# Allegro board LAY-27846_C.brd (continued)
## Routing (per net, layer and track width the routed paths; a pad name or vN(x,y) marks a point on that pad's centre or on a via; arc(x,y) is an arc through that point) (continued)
P5V0_SDA_USB_CONN_VBUS: length 4.2
  TOP w0.508: J15.1 10.26,40.46 11.32,41.52 L6.1
P5V_K24_USB: length 5
  TOP w0.178: L4.1 7.35,22.58 U10.1 7.13,20.38 J6.1
P5V_KW24_USB: length 57.6
  TOP w0.508: D15.C 13.06,20.81 v2(13.06,24.74) C50.1
  L3_PWR w0.508: J27.1 57.23,13.26 32.56,13.26 21.08,24.74 v2(13.06,24.74)
P5V_SDA: length 45
  TOP w0.508: v2(29.72,39.42) 29.72,40.97 27.18,43.51 C49.1 19.48,43.48 D13.C
  L3_PWR w0.508: v2(42.82,35.38) 42.8,35.38 v2(37.08,41.1) 30.68,41.1 29.72,40.13 v2(29.72,39.42)
  BOTTOM w0.178: v2(37.08,41.1) 37.07,41.11 U6.6 ; R52.1 29.29,38.99 v2(29.72,39.42) 28.32,39.42 TP104.1
  BOTTOM w0.508: R108.1 C33.1 C34.1 42.87,37.06 U7.1 42.12,36.08 v2(42.82,35.38)
P5V_USB: length 73.7
  TOP w0.508: v2(42.11,39.95) 42.11,46.28 v2(42.47,46.63)
  L3_PWR w0.508: v2(52.17,46.63) v2(42.47,46.63) 29.97,46.63 29.46,46.13 20.52,46.13 ; 13.7,22.41 J1.1 ; J1.1 15.31,22.41 ; J1.1 15.31,24.02 ; J1.1 13.7,24.02
  BOTTOM w0.178: J12.2 55.09,36.83 52.83,39.09 52.83,45.97 v2(52.17,46.63)
  BOTTOM w0.508: U7.6 42.12,39.94 v2(42.11,39.95) ; D12.A 16.36,16.1 15.77,16.69 15.77,21.95 J1.1 v2(14.5,27.53)
  vias: v2(6.96,44.7)
VCC: length 11.6
  TOP w0.508: J2.3 J2.1 ; J2.3 J2.5 ; J2.3 33.75,21.72 J3.2
  BOTTOM w0.33: J2.5 TP5.1
VDD_IF: length 8.1
  TOP w0.178: U3.54 69.03,30.06 70.33,31.37 C42.1 C43.1 ; C43.1 70.54,29.62 C44.1 69.98,29.06 U3.52 ; C43.1 70.28,30.35 69.49,29.56 U3.53
VDD_REGD: length 2.4
  TOP w0.178: C15.1 70.66,24.26 69.1,24.26 U3.43
CLK_OUT: length 10.3
  TOP w0.178: v2(65.96,19.48) 65.71,19.48 R83.1 ; v2(66.7,22.58) 66.7,22.91 66.7,22.91 U3.39
  BOTTOM w0.178: TP27.1 63.22,20.29 64.03,19.48 v2(65.96,19.48) 66.85,20.37 66.85,22.43 v2(66.7,22.58)
ELE_PS_SENSE: length 186.2
  TOP w0.178: v2(74.02,35.03) 73.96,35.03 73.08,35.92 73.08,55.88 74.7,57.51 74.7,63.83 75.08,64.21 75.08,65.43 v2(74.83,65.68) ; J16.D4 6.48,5.39 9.91,8.81 v2(11.28,8.81) ; v2(83.61,73.46) 83.61,76.49 83.48,76.62 J16.B4
  L2_GND w0.178: v2(74.22,9.96) 70.18,5.92 23.93,5.92 22.56,7.29 22.56,9.7 v1(19.94,12.32)
  L3_PWR w0.178: v2(74.83,65.68) 74.83,66.9 81.43,73.51 83.56,73.51 v2(83.61,73.46) ; v1(19.94,12.32) 19.94,18.64 21.31,20.02 v2(21.34,20.02) ; v2(74.02,35.03) 74.02,30.18 73.53,29.69 73.53,17.68 74.22,16.99 v2(74.22,9.96)
  BOTTOM w0.178: v2(11.28,8.81) 12.19,9.73 19.1,9.73 19.94,10.57 v1(19.94,12.32) ; v2(21.34,20.02) 21.59,20.27 37.21,20.27 38.41,21.46 38.41,25.25 40.06,26.9 R111.1
EXTAL_32: length 4.9
  TOP w0.178: R83.2 63.78,20.4 63.78,21.92 63.12,22.58 R82.2 62.7,22.59 U3.31
EXTAL_32K: length 3.7
  TOP w0.178: Y2.1 62.48,19.84 C23.1 62.69,20.8 R82.1
EXTAL_32M: length 8
  TOP w0.178: U3.1 68.2,34.54 C20.2 68.3,36.94 Y1.1 67.55,37.02 66.52,38.05 C21.1
EZP_CSR_B: length 20.2
  TOP w0.178: R27.2 2.54,45.59 1.24,46.89 1.24,52.83 2.11,53.7 J11.9 4.55,53.7 5.28,54.43 R26.2
GPIO1: length 88.9
  TOP w0.178: J16.D50 54.48,7.8 56.41,9.73 71.76,9.73 72.59,10.57 v2(72.59,19.43) ; J10.15 63.58,65.84 v1(65.02,67.28) ; v2(67.7,32.46) U3.2
  BOTTOM w0.178: v1(65.02,67.28) 65.02,67.03 67.7,64.36 v2(67.7,32.46) 67.7,31.49 72.59,26.59 v2(72.59,19.43)
GPIO2: length 92.5
  TOP w0.178: J16.D51 55.48,6.82 57.38,8.71 v2(59.41,8.71) ; v2(55.42,65.89) 55.47,65.84 J10.16 ; v2(67.89,30.58) 67.2,31.28 U3.3
  L3_PWR w0.178: v2(55.42,65.89) 65.07,65.89 v1(65.28,66.09)
  BOTTOM w0.178: v2(59.41,8.71) 70.05,8.71 71.6,10.27 71.6,26.87 v2(67.89,30.58) 67.18,31.29 67.18,64.19 v1(65.28,66.09)
GPT_VBRD: length 61.1
  TOP w0.178: J9.2 v1(65.1,56.95)
  L3_PWR w0.178: v2(26.8,56.77) 29.64,56.77 29.92,57.05 65,57.05 v1(65.1,56.95)
  BOTTOM w0.178: J8.2 12.12,60.71 22.86,60.71 v2(26.8,56.77)
GPT_VDA: length 17.4
  TOP w0.178: J9.4 64.97,58.22 64.06,57.3 v2(64.06,48.36)
  BOTTOM w0.178: R20.1 64.92,45.26 64.92,47.5 v2(64.06,48.36)
K24_USB_SHLD: length 18.9
  TOP w0.178: J6.S1 4.78,22.32 3.85,23.25 J6.S3 ; J6.S4 3.67,14.9 4.78,16 4.78,16.84
  TOP w0.508: J6.S4 1.78,14.91 ; L8.1 5.7,15.93 J6.S2 4.78,16.84
  BOTTOM w0.508: J6.S1 J6.S2
KW24_USB_DN: length 63.7
  TOP w0.178: J6.2 6.73,19.73 U11.1 7.35,19.59 v2(7.59,19.84)
  L2_GND w0.178: v2(7.59,19.84) 8.89,19.84 17.37,28.32 v2(28.14,28.32)
  L3_PWR w0.178: v2(28.14,28.32) 28.3,28.17 40.97,28.17 v2(41.88,27.25)
  BOTTOM w0.178: R33.1 53.97,29.08 51.71,26.82 51.71,22.12 50.9,21.31 48.95,21.31 44.37,25.88 42.21,25.88 41.88,26.21 v2(41.88,27.25)
KW24_USB_DP: length 59.8
  TOP w0.178: v2(7.35,18.34) U12.1 5.88,19.08 J6.3
  L2_GND w0.178: v2(27.48,27.84) 17.55,27.84 8.05,18.34 v2(7.35,18.34)
  L3_PWR w0.178: v2(27.48,27.84) 40.13,27.84 41.05,26.92 v2(41.05,26.95)
  BOTTOM w0.178: v2(41.05,26.95) 41.05,26.01 41.5,25.55 44.17,25.55 48.79,20.93 51.79,20.93 54.1,23.24 R34.1
POWER_EN: length 15.8
  L3_PWR w0.178: v2(40.94,40.77) 40.94,38.25 44.27,34.92 v2(44.27,31.52)
  BOTTOM w0.178: v2(40.94,40.77) 40.95,40.77 40.95,43.53 40.6,43.88 U6.31 ; R551.1 v2(44.27,31.52)
PTA0: length 87.9
  TOP w0.178: v2(45.24,22.48) 45.44,22.68 45.44,39.01 v2(45.19,39.27) ; U3.33 63.7,22.79 v2(63.7,22.78) ; J11.4 v2(9.5,57.51) ; v1(30.28,49.45) 30.28,49.25 34.77,44.75 v2(34.77,42.9)
  L3_PWR w0.178: v2(30.51,51.31) 20.07,51.31 13.87,57.51 v2(9.5,57.51) ; v2(34.77,42.9) 44.65,42.9 45.19,42.37 v2(45.19,39.27) ; v2(63.7,22.78) 45.54,22.78 v2(45.24,22.48)
  BOTTOM w0.178: v1(30.28,49.45) 30.51,49.68 v2(30.51,51.31) ; v2(45.19,39.27) 45.24,39.27 R93.2
PTA1: length 97.9
  TOP w0.178: J11.8 v1(10.67,54.97) ; U3.34 v2(64.2,24.79)
  L2_GND w0.178: v2(43.31,19.25) 46.28,22.23 46.28,47.32 v1(42.54,51.05)
  L3_PWR w0.178: v1(10.67,54.97) 10.67,54.05 11.86,52.86 17.88,52.86 19.91,50.83 v1(28.14,50.83) 42.32,50.83 v1(42.54,51.05) ; v2(43.31,19.25) 43.33,19.23 v2(62.03,19.23)
  BOTTOM w0.178: v2(64.2,24.79) 64.2,24.78 62.03,22.61 v2(62.03,19.23)
PTA2: length 90.9
  TOP w0.178: U3.35 v2(64.7,22.33) ; J11.6 7.75,56.11 24.28,56.11 26.97,53.42 v1(26.97,53.39)
  L3_PWR w0.178: v2(50.34,52.4) 27.97,52.4 v1(26.97,53.39) ; v2(50.9,22.33) v2(64.7,22.33)
  BOTTOM w0.178: v2(50.34,52.4) 50.34,46.38 51.89,44.83 51.89,31.14 51.23,30.48 51.23,22.63 50.93,22.33 v2(50.9,22.33)
PTA3: length 122.1
  TOP w0.178: R25.1 7.42,59.21 7.62,59 J11.2 6.35,58.78 v1(5.77,58.19) ; v2(65.2,21.87) U3.36
  L2_GND w0.178: v2(46.23,20.9) 46.69,21.36 46.69,38.51 v2(48.44,40.26)
  L3_PWR w0.178: v1(5.77,58.19) 4.5,56.92 4.5,34.34 7.67,31.17 8.89,31.17 13.49,26.57 32.61,26.57 33.86,25.32 41.4,25.32 45.83,20.9 v2(46.23,20.9) 47.2,21.87 v2(65.2,21.87)
  BOTTOM w0.178: v2(48.44,40.26) 48.44,43.38 R92.2
PTA4: length 74.1
  TOP w0.178: R27.1 v2(6.35,45.59) ; U3.37 v2(65.7,23.14)
  L3_PWR w0.178: v1(15.98,35.33) 15.98,34.47 21.59,28.85 28.73,28.85 28.96,28.63 41.17,28.63 41.71,28.09 v2(47.19,28.09) ; v2(65.7,23.14) 64.53,24.31 v2(47.19,24.31)
  BOTTOM w0.178: v1(15.98,35.33) 15.98,36.73 7.11,45.59 v2(6.35,45.59) ; v2(47.19,24.31) v2(47.19,28.09)
PTA19: length 26.5
  TOP w0.178: U3.40 v2(67.2,23.09) ; R564.2 72.01,45.16 72.59,44.58 v2(72.59,42.55)
  L3_PWR w0.178: v2(72.59,42.55) 72.59,42.57 72.77,42.39 72.77,32.87 68.45,28.55 68.45,26.67 67.59,25.81 67.59,23.48 v2(67.2,23.09)
PTB10_TWRPI: length 116.4
  TOP w0.178: v2(69.42,48.62) U13.4 68.13,50.2 R553.2 ; J10.11 v1(63.09,63.3) ; R73.1 13.18,68.19 J17.3 12.88,67.9 11.76,66.78 11.76,61.49 14.3,58.95 v2(21.67,58.95) ; J16.B9 78.48,74.39 77.95,73.86 77.95,71.35 74.35,67.74 v1(74.35,64.19)
  L2_GND w0.178: v2(44.81,59.41) 44.81,60.25 v1(48.16,63.6)
  L3_PWR w0.178: v1(48.16,63.6) 48.31,63.75 62.64,63.75 v1(63.09,63.3) 63.2,63.2 73.36,63.2 v1(74.35,64.19) ; v2(21.67,58.95) 21.72,59 28.96,59 29.36,59.41 v2(44.81,59.41)
  BOTTOM w0.178: v1(74.35,64.19) 74.35,62.76 74.78,62.33 74.78,60.48 72.72,58.42 72.72,49.25 72.09,48.62 TP506.1 v2(69.42,48.62)
PTB11_TWRPI: length 113.4
  TOP w0.178: v2(25.68,66.09) 26.26,66.67 R72.1 ; v2(69.49,46.13) 69.44,46.08 U13.2 67.34,46.08 66.62,46.79 66.62,49.71 R554.2 ; J16.B7 80.48,73.17 77.27,69.95 v2(77.27,69.98) ; v2(28.83,66.12) 28.8,66.09 v2(28.8,63.04) 29.39,62.46 43.54,62.46 v1(44.15,63.07) ; J10.12 v2(55.37,63.3)
  L3_PWR w0.178: v2(28.83,66.12) 28.8,66.09 v2(25.68,66.09) ; v2(75.74,63.32) 75.23,63.32 74.73,62.81 62.74,62.81 62.26,63.3 v2(55.37,63.3) 48.56,63.3 48.34,63.07 v1(44.15,63.07)
  BOTTOM w0.178: v2(25.68,66.09) 21.79,66.09 21.46,66.42 16.92,66.42 15.44,67.9 J17.6 ; v2(77.27,69.98) 75.74,68.45 v2(75.74,63.32) 75.74,60.6 73.66,58.52 73.66,56.59 73.08,56.01 73.08,47.75 72.01,46.69 TP504.1 70.89,46.13 v2(69.49,46.13)
PTB16_TWRPI: length 112.1
  TOP w0.178: J10.10 55.4,62.03 v2(55.37,62) ; J16.B10 v2(77.48,72.82) ; v2(69.55,44.58) 69.32,44.81 U13.1 66.78,44.81 65.56,46.02 65.56,49.68 R555.2 ; R71.1 24.26,66.75 24.71,66.29 v2(24.71,64.8)
  L3_PWR w0.178: v2(28.8,62) v2(55.37,62) 55.42,62.05 v2(74.24,62.05) ; J17.9 17.98,67.9 19.28,66.6 22.91,66.6 v2(24.71,64.8)
  BOTTOM w0.178: v2(24.71,64.8) 27.51,62 v2(28.8,62) ; TP500.1 71.25,44.58 v2(69.55,44.58) 68.96,45.16 68.96,50.11 72.26,53.42 72.26,58.55 74.24,60.53 v2(74.24,62.05) 74.3,62.05 73.89,62.46 73.89,69.24 77.47,72.82 v2(77.48,72.82)
PTB17_TWRPI: length 120.9
  TOP w0.178: v1(51.54,61.54) 45.62,61.54 43.54,59.46 v2(27.74,59.46) ; J10.9 62.38,62.03 v1(62.84,61.57) ; R552.2 65.13,50.27 65.13,45.44 64.49,44.81 U13.8 62.73,44.15 63.22,43.66 v2(68.68,43.66) ; J16.B11 76.48,71.73 74.88,70.13 v2(73.25,70.13) ; R70.1 20.5,67.9 J17.12 21.64,67.9 23.01,66.52 v2(23.01,62.64)
  L2_GND w0.178: v2(23.01,62.64) 24.56,62.64 v2(27.74,59.46)
  L3_PWR w0.178: v1(51.54,61.54) 62.81,61.54 v1(62.84,61.57) v1(73.79,61.57)
  BOTTOM w0.178: v2(73.25,70.13) 73.53,69.85 73.53,61.82 v1(73.79,61.57) 73.79,60.63 71.76,58.6 71.76,53.47 68.53,50.24 68.53,43.81 v2(68.68,43.66) 69.52,42.82 TP501.1
PTC4: length 104.4
  TOP w0.178: J17.2 14.27,63.97 14.27,60.22 14.91,59.59 22.5,59.59 v2(22.83,59.92) ; R78.1 67.31,35.99 v2(66.7,36.6) ; v1(48.62,67.11) 52.37,67.11 53.44,66.04 v2(53.44,60.35) 53.47,60.35 53.97,59.84 SW1.3 ; SW1.4 SW1.3 ; SW1.3 53.42,52.27 v2(52.83,52.86)
  L3_PWR w0.178: v2(22.83,59.92) 53.01,59.92 v2(53.44,60.35) ; v2(52.83,52.86) 53.01,53.04 v2(66.7,53.04)
  BOTTOM w0.178: v2(66.7,53.04) v2(66.7,36.6) ; v1(48.62,67.11) R66.2
PTC4_A: length 41.2
  TOP w0.178: v2(41.1,71.88) 39.48,73.5 J16.B46
  BOTTOM w0.178: J17.1 13.31,62.82 14.91,61.21 29.21,61.21 29.97,61.98 29.97,65.46 36.4,71.88 v2(41.1,71.88)
PTC5: length 108.9
  TOP w0.178: R79.1 66.37,36.3 66.14,36.53 v2(66.14,37.44) ; SW2.4 SW2.3 53.95,46.91 v2(54,46.96)
  L2_GND w0.178: J17.5 16.61,64.17 16.61,62.1 17.42,61.29 25.27,61.29 29.24,57.33 v2(29.46,57.33) ; v2(49.99,57.51) 50.52,56.97 50.52,54.15 54,50.67 v2(54,46.96)
  L3_PWR w0.178: v2(49.99,57.51) 49.86,57.38 29.51,57.38 v2(29.46,57.33) ; v2(66.14,48.95) 55.98,48.95 v2(54,46.96)
  BOTTOM w0.178: v2(54,46.96) 55.45,48.41 55.45,54.71 60.66,59.92 R67.2 ; v2(66.14,48.95) v2(66.14,37.44)
PTC5_A: length 32.1
  TOP w0.178: v2(17.12,64.06) 15.88,62.82 J17.4 ; J16.B48 37.48,72.97 31.88,67.36 v2(31.88,64.29)
  L3_PWR w0.178: v2(31.88,64.29) 31.65,64.06 v2(17.12,64.06)
PTC6: length 91.7
  TOP w0.178: R80.1 65.23,34.47 v2(65.23,35.59) ; v2(54.61,65.56) 54.84,65.33 54.84,39.62 53.97,38.76 v2(53.97,37.19) SW3.3 SW3.4
  L3_PWR w0.178: v2(65.23,35.59) 55.58,35.59 v2(53.97,37.19) ; v2(54.61,65.56) 54.13,66.04 43.31,66.04 42.11,67.23 33.78,67.23 31.83,65.28 v2(27.36,65.28)
  BOTTOM w0.178: R68.2 27.66,68.07 27.36,67.77 v2(27.36,65.28) 22.5,65.28 21.54,64.31 18.49,64.31 17.96,64.84 J17.8
PTC6_A: length 34
  TOP w0.178: J16.B45 v2(40.48,73.84)
  BOTTOM w0.178: J17.7 19.24,61.54 29.03,61.54 29.57,62.08 29.57,65.68 36.14,72.26 39.88,72.26 40.48,72.87 v2(40.48,73.84)
PTC7: length 110.2
  TOP w0.178: R81.1 64.69,36.32 65.18,36.8 v2(65.18,37.92) ; v2(32.44,53.59) 30.84,53.59 25.78,58.65 25.78,65.46 27,66.67 v2(27,68.07) ; SW4.4 SW4.3 54.94,25.32 v2(54.94,37.92)
  L3_PWR w0.178: v2(65.18,37.92) v2(54.94,37.92) ; v2(65.61,54.33) 65.56,54.28 52.48,54.28 51.79,53.59 v2(32.44,53.59)
  BOTTOM w0.178: v2(65.61,54.33) 65.61,38.35 v2(65.18,37.92) ; R69.2 27,69.04 v2(27,68.07) 27,66.55 26.06,65.61 20.76,65.61 J17.11
PTC7_A: length 35
  TOP w0.178: J16.B44 41.48,72.69 42.14,72.03 v2(42.14,70.41)
  L2_GND w0.178: v2(32.77,63.73) 32.77,68.94 34.54,70.71 41.83,70.71 v2(42.14,70.41)
  L3_PWR w0.178: J17.10 20.5,62.82 21.44,63.75 32.74,63.75 v2(32.77,63.73)
PTD1: length 106.5
  TOP w0.178: v2(23.72,63.3) 23.72,66.29 22.33,67.69 22.33,76.6 22.48,76.76 J16.B63 ; v2(63.3,34.85) 63.3,34.29 64.7,32.89 U3.8 ; J9.9 72.8,62.03 73.3,61.52 v2(73.3,60.86)
  L2_GND w0.178: v2(50.85,57.58) 50.85,54.38 51.41,53.82 v2(52.88,53.82) ; v2(30.38,57.86) 30.07,57.86 24.64,63.3 v2(23.72,63.3)
  L3_PWR w0.178: v2(50.85,57.58) 50.85,57.68 50.55,57.99 48.16,57.99 47.9,57.73 30.51,57.73 v2(30.38,57.86) ; v2(62.88,52.55) 67.01,52.55 v2(68.28,53.82) v2(62.2,53.82) v2(52.88,53.82)
  BOTTOM w0.178: v2(63.3,34.85) 63.3,34.82 61.75,36.37 61.75,41.35 62.88,42.48 v2(62.88,42.49) 62.89,42.51 62.89,52.54 v2(62.88,52.55) ; v2(68.28,53.82) 68.12,53.98 68.12,56.41 72.57,60.86 v2(73.3,60.86)
PTD2: length 146.3
  TOP w0.178: U3.9 64.2,32.73 61.21,35.71 61.21,50.95 v2(62.18,51.92) 62.18,53.06 63.07,53.95 v2(63.07,58.22) J10.3 ; J16.B52 33.48,74.33 v2(32.99,73.84) 32.41,73.25 23.39,73.25 22.66,72.52 22.66,68.88 R77.2 23.24,67.28 24.21,66.32 v2(24.21,57.79)
  L3_PWR w0.178: v2(24.21,57.79) 24.69,57.3 24.69,52.5 25.27,51.92 v2(62.18,51.92) ; v2(63.07,58.22) v2(74.12,58.22)
  BOTTOM w0.178: J16.A53 32.48,74.78 32.99,74.27 v2(32.99,73.84) 31.5,73.84 30.58,72.92 30.58,69.75 R21.2 ; J16.A7 80.48,72.25 77.09,68.86 R74.1 76.91,68.83 76.2,68.12 76.2,60.3 v2(74.12,58.22)
PTD3: length 125.5
  TOP w0.178: U3.10 63.7,32.59 60.81,35.48 60.81,52.4 60.32,52.88 56.31,52.88 55.19,54 55.19,57.99 v2(55.42,58.22) J10.4
  L2_GND w0.178: v2(55.42,58.22) 61.9,64.69 v1(61.9,69.62)
  L3_PWR w0.178: v1(76.78,70.84) v2(70.82,70.84) 70.69,70.84 69.88,71.65 62.66,71.65 v2(61.9,72.42) 61.87,72.39 v2(35.48,72.39) 33.45,72.39 32.99,71.93 v2(29.01,71.93) v2(25.48,71.93)
  BOTTOM w0.178: v2(61.9,72.42) v1(61.9,69.62) ; J16.A8 79.48,73.54 v1(76.78,70.84) ; R22.2 v2(29.01,71.93) ; R76.2 R75.2 68.55,68.58 70.08,68.58 70.82,69.32 v2(70.82,70.84) ; J16.A60 v2(25.48,71.93)
PTD4: length 99.4
  TOP w0.178: v2(38.43,70.26) 38.48,70.31 J16.B47 ; v2(62.18,33.25) 63.2,32.23 U3.11 ; v2(49.68,29.95) v2(49.68,14.81)
  L2_GND w0.178: v2(38.43,70.26) 38.43,67.39 37.97,66.93 37.97,59.97 38.33,59.61 38.33,31.11 v2(37.54,30.33)
  L3_PWR w0.178: v2(37.54,30.33) 37.57,30.3 42.21,30.3 42.88,29.64 49.38,29.64 v2(49.68,29.95) 49.71,29.95 53.01,33.25 v2(62.18,33.25)
  BOTTOM w0.178: v2(49.68,14.81) 49.12,14.25 44.63,14.25 42.39,12.01 J19.2
PTD4_LED: length 7.4
  TOP w0.178: J19.3 44.96,12.01 48.26,15.32 R16.2
PTD4_TWR: length 81.1
  L2_GND w0.178: v2(7.61,73.84) 7.61,73.82 11.33,70.1 11.33,59.31 32.49,38.15 32.49,14.91 33.93,13.46 38.39,13.46 J19.1
  BOTTOM w0.178: J16.A78 7.48,73.95 7.59,73.84 v2(7.61,73.84)
PTD5: length 48.4
  TOP w0.178: v2(62.31,32.44) 62.7,32.04 U3.12 ; J20.2 33.46,15.47 35.33,17.35 35.33,29.64 v2(35.48,29.79)
  L3_PWR w0.178: v2(35.48,29.79) 41.96,29.79 42.52,29.24 49.63,29.24 53.34,32.94 61.8,32.94 v2(62.31,32.44)
PTD5_LED: length 31.9
  TOP w0.178: R17.2 48.26,29.11 49.23,28.14 49.23,13.94 47.57,12.29 v2(47.57,10.74)
  L3_PWR w0.178: v2(47.57,10.74) 37.26,10.74 36,12.01 J20.3
PTD5_TWR: length 76.2
  L2_GND w0.178: J20.1 31.98,13.07 31.98,37.9 10.95,58.93 10.95,69.75 6.83,73.86 v2(6.61,73.86)
  BOTTOM w0.178: J16.A79 6.48,73.98 6.6,73.86 v2(6.61,73.86)
PTD6: length 30.6
  TOP w0.178: U3.13 62.2,31.88 61.59,32.49 v2(60.91,32.49)
  L3_PWR w0.178: v2(55.93,10.41) 53.63,10.41 J21.2
  BOTTOM w0.178: v2(55.93,10.41) 55.93,14.94 61.06,20.07 61.06,32.33 v2(60.91,32.49)
PTD6_LED: length 37.5
  TOP w0.178: v2(46.69,15.27) 46.69,39.57 R18.2 ; J21.3 v2(54.59,14.86)
  L3_PWR w0.178: v2(46.69,15.27) 50.22,15.27 50.62,14.86 v2(54.59,14.86)
PTD6_TWR: length 116.5
  L2_GND w0.178: J21.1 49.15,12.35 49.15,15.29 51.41,17.55 51.41,28.5 52.81,29.9 52.81,44.6 55.19,46.99 55.19,55.75 50.67,60.27 v1(50.67,67.56)
  L3_PWR w0.178: v2(5.56,73.91) 5.64,73.91 6.05,74.32 44.25,74.32 v2(44.68,73.89) ; v2(47.85,67.54) 47.88,67.56 v1(50.67,67.56)
  BOTTOM w0.178: J16.A80 5.48,73.99 v2(5.56,73.91) ; J16.A41 44.48,74.08 v2(44.68,73.89) 44.68,72.39 R64.1 47.4,69.7 47.85,69.24 v2(47.85,67.54)
PTD7: length 37.4
  TOP w0.178: v2(60.32,31.93) 61.52,31.93 61.7,31.75 U3.14 ; v2(55.42,14.81) v2(55.42,32)
  L3_PWR w0.178: v2(60.32,31.93) 55.5,31.93 v2(55.42,32) ; J24.2 43.85,14.25 54.86,14.25 v2(55.42,14.81)
PTD7_LED: length 34.3
  TOP w0.178: J24.3 45.02,15.63 45.52,16.13 45.52,21.31 46.2,22 46.2,49.07 R19.2
PTD7_TWR: length 63.3
  TOP w0.178: v2(40.59,19.46) 40.59,16.28 J24.1
  L2_GND w0.178: v2(40.59,19.46) 40.59,31.85 40.21,32.23 40.21,49.83 43.61,53.24 v2(43.61,73.84)
  BOTTOM w0.178: J16.A42 43.48,73.97 v2(43.61,73.84)
PTE0: length 117.5
  TOP w0.178: J11.12 v1(5.64,52.43) ; v2(52.81,68.55) 53.72,69.47 R58.1 ; U3.15 60.58,31.06 60.43,31.22 v2(60.4,31.22) ; v2(59.87,47.7) v2(59.87,50.62)
  L2_GND w0.178: v2(31.88,56.44) v1(31.88,50.37) ; v2(35.26,68.55) 35.26,64.66 J18.2
  L3_PWR w0.178: v2(52.81,68.55) 52.65,68.4 47.4,68.4 47.24,68.55 v2(35.26,68.55) ; v2(59.87,50.62) 46.13,50.62 45.9,50.85 43.18,50.85 42.7,50.37 v1(31.88,50.37) 19.76,50.37 17.7,52.43 v1(5.64,52.43)
  BOTTOM w0.178: v2(60.4,31.22) 59.87,31.75 v2(59.87,47.7) ; v2(31.88,56.44) 31.88,62.15 33.28,63.55 J18.2
PTE0_TWR: length 55.7
  TOP w0.178: R65.1 54.76,69.7 53.11,68.05 v1(46.91,68.05)
  L2_GND w0.178: J18.1 35.56,62.43 35.56,67.84 v2(35.71,68)
  L3_PWR w0.178: v1(46.91,68.05) 46.86,68 v2(35.71,68)
  BOTTOM w0.178: R88.2 45.62,52.2 46.91,53.49 v1(46.91,68.05) 46.91,68.55 41.48,73.99 J16.A44
PTE0_TWRPI: length 36.6
  TOP w0.178: J9.8 65.99,60.76 64.01,62.74 v1(64.01,64.47)
  L3_PWR w0.178: v1(64.01,64.47) 63.78,64.69 36.53,64.69 35.13,66.09 J18.3
PTE1: length 108.2
  TOP w0.178: v2(60.32,30.56) 60.33,30.56 U3.16 ; v2(47.32,49.91) 47.32,47.83 47.12,47.62 v2(47.12,44.09) ; J11.20 v1(10.21,47.35)
  L3_PWR w0.178: v2(60.32,30.56) 59.79,30.02 v2(51.87,30.02) ; v1(32.66,49.45) 43.54,49.45 43.99,49.91 v2(47.32,49.91) ; v1(10.21,47.35) 11.86,45.69 18.59,45.69 20.55,43.74 43.54,43.74 44.25,44.45 46.76,44.45 v2(47.12,44.09) 47.47,43.74 51.31,43.74 52.37,42.67 v2(52.35,42.67)
  BOTTOM w0.178: v2(52.35,42.67) 52.35,30.51 v2(51.87,30.02) ; J18.5 35.69,62.56 32.99,62.56 32.31,61.87 32.31,58.37 32.97,57.71 32.97,49.76 v1(32.66,49.45)
PTE1_TWR: length 55.8
  L2_GND w0.178: v2(36.7,58.19) 36.7,61 J18.4
  L3_PWR w0.178: v2(36.7,58.19) 36.74,58.23 v2(47.4,58.23)
  BOTTOM w0.178: R89.2 45.64,51.18 47.22,52.76 47.22,58.06 v2(47.4,58.23) ; v2(47.4,58.23) 53.36,58.23 56.64,61.52 R62.2 ; v2(47.4,58.23) 47.4,68.55 42.48,73.47 J16.A43
PTE1_TWRPI: length 53.5
  TOP w0.178: v1(65.51,63.7) 65.51,63.49 65.7,63.3 J9.12 ; R60.1 51.59,70.13 v2(50.77,69.32)
  L2_GND w0.178: v2(36.7,69.32) 36.7,66.11 J18.6
  L3_PWR w0.178: v1(44.09,64.01) 44.17,64.08 63.4,64.08 63.78,63.7 v1(65.51,63.7) ; v2(50.77,69.32) 41.17,69.32 41.02,69.47 36.86,69.47 v2(36.7,69.32)
  BOTTOM w0.178: J18.6 38.1,67.51 43.13,67.51 44.09,66.55 v1(44.09,64.01)
PTE2: length 97.1
  TOP w0.178: U3.17 60.64,30.06 v2(60.4,29.82) ; v1(28.6,44.96) 17.91,44.96 14.25,48.62 J11.18 ; v2(55.88,29.45) v2(55.88,43.48)
  L3_PWR w0.178: v2(60.4,29.82) 60.03,29.45 v2(55.88,29.45) ; v2(55.88,43.48) 53.37,46 33.3,46 32.82,45.52 29.16,45.52 v1(28.6,44.96)
  BOTTOM w0.178: J18.8 37.9,62.23 33.4,62.23 32.82,61.65 32.82,58.72 33.45,58.09 33.45,49.53 28.88,44.96 v1(28.6,44.96)
PTE2_TWR: length 81.9
  TOP w0.178: v2(46.35,59.39) v2(46.35,55.47) 46.66,55.78 v2(49.78,55.78)
  L2_GND w0.178: v1(64.14,59.74) 66.47,62.08 66.47,71.27 v2(65.56,72.19)
  L3_PWR w0.178: v2(46.35,59.39) 53.29,59.39 53.64,59.74 v1(64.14,59.74) ; v2(65.56,72.19) 70,72.19 70.79,71.4 77.67,71.4 78.48,72.21 v2(78.48,73.66)
  BOTTOM w0.178: R90.2 45.42,54.53 v2(46.35,55.47) ; v2(49.78,55.78) 54.36,55.78 58.65,60.07 R59.2 ; J18.7 40.27,59.97 45.77,59.97 v2(46.35,59.39) ; J16.A9 v2(78.48,73.66)
PTE2_TWRPI: length 55.2
  TOP w0.178: v2(28.47,57.35) 28.47,57.86 R23.2 ; J9.17 v1(73.03,67.11)
  L3_PWR w0.178: v1(73.03,67.11) 67.36,67.11 65.3,65.05 40.27,65.05 J18.9
  BOTTOM w0.178: v2(28.47,57.35) 28.47,58.65 30.91,61.09 30.91,64.03 31.98,65.1 38.23,65.1 J18.9
PTE3: length 102.9
  TOP w0.178: U3.18 61.52,29.56 61.98,30.02 v2(61.98,30.56) ; v1(28.93,47.19) 28.93,48.21 25.96,51.18 17.53,51.18 16.23,49.89 J11.16
  L3_PWR w0.178: v1(28.93,47.19) 29.03,47.29 41.3,47.29 41.83,47.83 47.5,47.83 47.9,47.42 52.58,47.42 53.62,46.38 v2(60.32,46.38)
  BOTTOM w0.178: v1(28.93,47.19) 28.93,58.5 31.32,60.88 31.32,63.07 32.94,64.69 40.62,64.69 J18.11 ; v2(60.32,46.38) 60.32,36.17 61.57,34.92 61.57,30.96 v2(61.98,30.56)
PTE3_TWR: length 70.8
  TOP w0.178: v2(64.49,72.24) 64.48,72.24 J16.B21 ; v2(51.23,68.86) 51.43,68.86 R61.2 ; v1(48.41,61.04) 47.09,61.04 45.9,59.84 45.9,55.22 v2(46.33,54.79)
  L2_GND w0.178: J18.10 40.64,62.14 v2(40.64,69.01)
  L3_PWR w0.178: v2(40.64,69.01) 40.79,68.86 v2(51.23,68.86) ; J18.10 48.39,61.01 v1(48.41,61.04) 64.46,61.04 v2(64.48,61.01)
  BOTTOM w0.178: v2(46.33,54.79) 46.33,53.85 45.69,53.21 R91.2 ; v2(64.49,72.24) 64.47,72.24 63.88,71.65 63.88,65.51 64.48,64.9 v2(64.48,61.01)
PTE3_TWRPI: length 72.5
  TOP w0.178: v1(49.15,65.58) 42.28,65.58 J18.12 ; v1(65.07,59.41) 65.07,61.14 63.55,62.66 63.55,65.18 65.48,67.11 J9.18
  L3_PWR w0.178: v2(29.97,58.85) v2(48.51,58.85) 53.47,58.85 53.9,59.28 64.95,59.28 v1(65.07,59.41)
  BOTTOM w0.178: v2(48.51,58.85) 49.15,59.49 v1(49.15,65.58) 50.11,65.58 51.69,67.16 R63.1 ; R24.2 29.97,56.13 30.96,57.12 30.96,58.42 30.53,58.85 v2(29.97,58.85)
PTE4: length 106.7
  TOP w0.178: v2(71.4,43.81) 70.76,43.81 69.32,42.37 R566.2 ; J11.14 v1(5.64,51.16) ; v2(60.38,29.06) U3.19 ; v2(52.93,28.85) v2(52.93,48.74)
  L3_PWR w0.178: v2(60.38,29.06) 60.17,28.85 v2(52.93,28.85) ; v1(5.64,51.16) 17.88,51.16 21.18,47.85 41.4,47.85 41.99,48.44 52.63,48.44 v2(52.93,48.74) 52.93,48.79 53.72,49.58 69.37,49.58 71.4,47.55 v2(71.4,43.81)
PTE16/UART2_TX: length 91.8
  TOP w0.178: v2(45.16,55.42) 45.16,52.48 45.8,51.84 45.8,22.23 44.98,21.41 v2(44.98,17.55) ; J10.18 v2(55.27,67.11)
  L2_GND w0.178: v2(45.16,55.42) 44.15,56.44 44.15,61.39 v1(49.3,66.55)
  L3_PWR w0.178: v2(55.27,67.11) 54.71,66.55 v1(49.3,66.55) ; v2(44.98,17.55) 53.52,17.55 v2(54.76,16.31)
  BOTTOM w0.178: J16.C42 46.48,6.53 45.26,7.75 45.26,8.41 44.53,9.14 43.1,9.14 41.17,11.07 41.17,16.31 42.42,17.55 v2(44.98,17.55) ; R84.1 v2(54.76,16.31)
PTE16/UART2_TX/USB_DP: length 21.1
  TOP w0.178: U3.21 v2(60.35,28.06)
  L2_GND w0.178: v2(58.17,18.21) 58.17,24.46 v1(56.34,26.29)
  L3_PWR w0.178: v1(56.34,26.29) 56.34,27.03 57.37,28.06 v2(60.35,28.06)
  BOTTOM w0.178: v2(58.17,18.21) 58.01,18.36 R84.2 ; v1(56.34,26.29) 55.65,25.6 C48.1 R34.2
PTE17/UART2_RX: length 110
  TOP w0.178: J10.17 v1(62.92,67.11)
  L2_GND w0.178: v2(43.13,56.44) 38.81,52.12 38.81,22.5 38.1,21.79 38.1,15.8 39.85,14.05 45.7,14.05 46.84,12.91 v2(46.84,11.99)
  L3_PWR w0.178: v2(46.84,11.99) 47.7,11.99 48.41,11.28 48.41,9.93 47.73,9.25 44.12,9.25 43.61,8.74 v2(43.61,7.82) ; v2(61.93,55.52) 61.93,56.03 61.21,56.74 43.43,56.74 v2(43.13,56.44)
  BOTTOM w0.178: v2(46.84,11.99) 48.31,13.46 49.99,13.46 51.28,14.76 51.28,17.25 R85.1 ; v1(62.92,67.11) 61.93,66.12 v2(61.93,55.52) ; J16.C41 45.48,5.95 v2(43.61,7.82)
PTE17/UART2_RX/USB_DN: length 19.1
  TOP w0.178: v2(57.73,27.56) U3.22
  BOTTOM w0.178: R85.2 52.1,19.08 52.81,19.08 57.73,24 v2(57.73,27.56) 55.81,27.56 C35.1 R33.2
PTE18/UART2_CTS: length 94.3
  TOP w0.178: v1(63.04,69.11) 62.31,68.38 J10.19
  L2_GND w0.178: v2(61.24,55.93) 60.71,56.46 56.97,56.46 56.03,55.52 56.03,46.46 53.52,43.94 53.52,28.78 52.25,27.51 52.25,18.08 53.44,16.89 53.44,8.33 52.35,7.24 48.26,7.24 v2(47.57,7.92)
  BOTTOM w0.178: J16.C44 48.48,7.02 v2(47.57,7.92) 50.67,11.02 50.67,12.6 52.48,14.4 R86.1 ; v1(63.04,69.11) 63.04,67.92 61.54,66.42 61.54,56.24 v2(61.24,55.93)
PTE18/UART2_CTS/VOUT33: length 70.9
  TOP w0.178: v2(58.37,27.08) 58.38,27.06 U3.23
  TOP w0.508: D14.A 32.92,27.18 v2(34.14,25.96)
  L3_PWR w0.508: v2(58.37,27.08) 58.37,26.42 56.95,24.99 49.25,24.99 48.29,25.96 v2(34.14,25.96)
  BOTTOM w0.178: C28.1 C27.1 58.14,52.15 v2(59.03,51.26) 59.39,50.9 59.39,31.72 59.87,31.24 59.87,29.13 58.37,27.64 v2(58.37,27.08) 58.37,23.98 52.81,18.41 R86.2
PTE19/UART2_RTS: length 84.7
  TOP w0.178: J10.20 v2(55.37,68.38) ; v2(46.61,7.82) 47.52,8.74 v2(50.8,8.74)
  L2_GND w0.178: v2(50.8,8.74) 53.09,11.02 53.09,16.46 51.82,17.73 51.82,28.4 53.16,29.74 53.16,44.27 55.58,46.69 55.58,56.06 54.05,57.58 54.05,67.06 v2(55.37,68.38)
  BOTTOM w0.178: J16.C43 47.48,6.95 v2(46.61,7.82) ; v2(50.8,8.74) 53.57,11.51 R87.1
PTE19/UART2_RTS/VREGIN: length 27.7
  TOP w0.178: v2(59.41,26.57) 59.42,26.56 U3.24
  L2_GND w0.178: J27.2 59.03,14 59.03,26.19 v2(59.41,26.57)
  BOTTOM w0.178: v2(59.41,26.57) 59.41,24.38 53.57,18.54 R87.2
RESET_B: length 9.8
  TOP w0.178: v2(24.31,42.85) 22.4,40.94 v2(20.24,40.94)
  BOTTOM w0.178: R94.2 25.2,43.74 v2(24.31,42.85) ; v2(20.24,40.94) 18.64,42.55 U14.3
RF_50: length 3.7
  TOP w0.333: Z1.1 76.67,28.41 C19.1 L5.1 C17.1
RF_ANT: length 2.1
  TOP w0.333: C18.1 82.4,28.4 ANT1.1
RST_TGTMCU_B: length 164.5
  TOP w0.178: v1(65.18,68.35) 65.2,68.38 J9.20 ; C29.1 SW6.2 SW6.1 19.76,47.57 v1(20.65,47.57) ; D9.C v2(11.4,51.89) 9.6,53.7 J11.10 ; v2(58.5,50.06) 58.5,51.59 59.33,52.43 v2(60.05,52.43) ; v2(67.61,22.43) 67.7,22.51 U3.41
  L3_PWR w0.178: v2(67.61,22.43) 68.02,22.83 68.02,25.65 68.86,26.49 68.86,28.35 73.1,32.59 73.1,46.51 69.55,50.06 v2(58.5,50.06) 53.37,50.06 52.27,48.97 20.6,48.97 17.68,51.89 v2(11.4,51.89)
  BOTTOM w0.178: R561.2 11.96,52.45 v2(11.4,51.89) R560.2 17.83,50.39 v1(20.65,47.57) 23.37,44.86 23.37,36.96 J29.1 ; v2(60.05,52.43) 62.97,55.35 65.3,55.35 66.65,56.69 66.65,63.8 64.57,65.89 64.57,67.74 v1(65.18,68.35)
RSTR: length 1.7
  TOP w0.508: D9.A 14.68,51.9 R46.2
SDA_EXTAL: length 4
  BOTTOM w0.178: Y3.3 35.43,49.76 C31.1 36.07,49.12 U6.17
SDA_JTAG_TCLK: length 17.2
  L2_GND w0.178: v2(33.12,44.81) 32.72,44.4 v2(31.37,44.4)
  BOTTOM w0.178: U6.12 33.2,44.89 v2(33.12,44.81) ; TP509.1 29.87,42.9 v2(31.37,44.4) 31.55,44.22 31.55,38.33 33.78,36.09 J13.4
SDA_JTAG_TDI: length 17.2
  TOP w0.178: v2(32.44,45.03) v2(31.34,45.03)
  BOTTOM w0.178: J13.8 33.2,38.63 32.44,39.4 v2(32.44,45.03) 32.72,45.03 33.07,45.39 U6.13 ; TP511.1 28.57,42.27 v2(31.34,45.03)
SDA_JTAG_TDO: length 18
  BOTTOM w0.178: J13.6 33.5,37.36 31.9,38.96 31.9,45.85 v2(32.03,45.97) ; v2(32.03,45.97) 31.52,45.97 29.41,43.87 TP510.1 ; v2(32.03,45.97) 35.33,45.97 U6.14
SDA_JTAG_TMS: length 24.3
  TOP w0.178: J13.2 33.66,34.82 32.41,36.07 32.41,40.51 33.78,41.88 33.78,45.11 32.31,46.58 31.47,46.58 v2(30.91,46.02)
  BOTTOM w0.178: v2(30.91,46.02) 32.08,47.19 TP508.1 32.69,46.69 32.99,46.39 U6.15
  BOTTOM w0.508: R107.2 33.38,33.48 J13.2
SDA_LED: length 39.1
  TOP w0.178: D11.C v2(22.12,57.28) 24.46,57.28 29.67,52.07 40.51,52.07 43.56,49.02 v2(43.56,44.45)
  BOTTOM w0.178: U6.29 43.13,44.89 v2(43.56,44.45) ; v2(22.12,57.28) TP106.1
SDA_LED_R: length 1.9
  TOP w0.178: R104.2 D11.A
SDA_RST: length 25.1
  L2_GND w0.178: v2(37.07,48.51) 37.07,47.87 32.99,43.79 v2(32.99,39.9)
  L3_PWR w0.178: v2(31.09,40.44) 32.46,40.44 v2(32.99,39.9)
  BOTTOM w0.178: TP512.1 30.81,40.72 v2(31.09,40.44) 31.09,35.76 R100.1 29.31,35.61 R52.2 29.29,34.37 TP105.1 ; v2(32.99,39.9) J13.10 ; v2(37.07,48.51) U6.19
SDA_SPI0_SCK: length 9.6
  L2_GND w0.178: v2(42.04,47.32) 41.88,47.17 41.88,45.03 v2(44.55,42.37)
  BOTTOM w0.178: v2(42.04,47.32) 42.04,47.09 41.33,46.39 U6.26 ; U4.12 44.54,42.35 v2(44.55,42.37)
SDA_SPI0_SIN: length 12
  BOTTOM w0.178: R112.1 47.14,39.4 U4.8 47.12,41.22 47.12,43.33 46.02,44.42 44.78,44.42 43.82,45.39 U6.28
SDA_SPI0_SOUT: length 5.6
  BOTTOM w0.178: U4.2 43.89,46.58 43.19,45.89 U6.27
SDA_SWD_EN: length 27.6
  TOP w0.178: v2(43.89,39.57) 43.51,39.19 39.88,39.19 39.07,40 39.07,45.69 36.42,48.34 v2(35.42,48.34) 36.08,49 38.28,49 R106.2
  BOTTOM w0.178: U6.16 v2(35.42,48.34) ; U4.10 45.84,42.28 45.26,42.85 44.32,42.85 43.89,42.41 U4.13 v2(43.89,39.57)
SDA_SWD_OE_B: length 7.6
  TOP w0.178: R105.1 41.15,48.56 v2(41.3,48.41)
  L3_PWR w0.178: v2(37.74,48.36) 37.8,48.41 v2(41.3,48.41)
  BOTTOM w0.178: v2(37.74,48.36) 37.75,48.36 37.57,48.18 U6.20 ; U4.1 43.03,48.41 v2(41.3,48.41)
SDA_USB_CONN_DN: length 20.9
  TOP w0.178: v2(4.95,39.66) J15.2 14.34,39.66 15.01,40.34 U8.1
  BOTTOM w0.178: v2(4.95,39.66) 4.95,35.89 R50.1
SDA_USB_CONN_DP: length 18.9
  TOP w0.178: v2(5.44,38.86) J15.3 14.62,38.86 U8.2
  BOTTOM w0.178: v2(5.44,38.86) 5.36,38.79 5.36,36.27 9.42,32.21 R51.1
SDA_USB_DN: length 43.9
  L3_PWR w0.178: v1(36.14,26.92) 36.09,26.97 22.07,26.97 17.93,31.11 v2(15.16,31.11)
  BOTTOM w0.178: v2(15.16,31.11) R50.2 ; v1(36.14,26.92) 36.14,27.28 38.23,29.36 38.23,42.21 38.07,42.37 U6.4
SDA_USB_DP: length 43.7
  L3_PWR w0.178: v1(36.91,27.38) 22.38,27.38 17.55,32.21 v2(15.14,32.21)
  BOTTOM w0.178: U6.3 38.57,29.1 36.91,27.43 v1(36.91,27.38) ; v2(15.14,32.21) R51.2
SDA_USB_VOUT33: length 96.8
  TOP w0.178: R104.1 11.79,56.85 12.14,56.49 24.64,56.49 36.57,44.56 v2(36.57,41.86) 35.19,41.86 34.32,42.73 v2(34.32,44.37)
  TOP w0.508: R106.1 39.22,47.04 R105.2 40.31,41.94 v2(39.57,41.2) ; J13.1 36.47,34.82 R110.1 38.2,29.82 37.67,29.29 v2(37.21,29.29) ; v2(42.95,39.83) 45.19,42.06 v2(45.19,49.45)
  L3_PWR w0.508: 37.36,34.06 J13.1 35.99,34.06
  BOTTOM w0.178: TP103.1 33.45,44.37 v2(34.32,44.37) 34.33,44.39 U6.11 ; U4.14 43.24,40.11 v2(42.95,39.83) ; v2(39.57,41.2) 39.57,41.2 U6.1 ; U6.5 37.57,41.47 37.85,41.2 37.85,31.65 37.49,31.29 C32.1 ; v2(36.57,41.86) U6.7 ; U4.4 v2(45.19,49.45)
  BOTTOM w0.508: v2(37.21,29.29) 36.86,29.29 C26.1 ; C26.1 C32.1 ; C26.1 R107.1 ; v2(22.45,42.04) 22.45,44.17 21.34,45.29 D16.A
SDA_USBSHIELD: length 22.8
  TOP w0.508: J15.S2 J15.S4 J15.S3 J15.S1 ; J15.S2 12.15,34.41 L7.1 ; J15.S2 9.27,34.4
SDA_XTAL: length 8.5
  BOTTOM w0.178: U6.18 36.57,48.99 C30.1 36.5,49.89 36.5,52.78 37.83,54.11 Y3.1
SWD_CLK_TGTMCU: length 2.4
  BOTTOM w0.178: R93.1 45.19,40.34 U4.11
SWD_DIO_TGTMCU: length 14.4
  TOP w0.178: v2(44.53,43.97) v2(44.53,45.54)
  BOTTOM w0.178: R92.1 46.43,45.54 45.77,44.88 44.98,44.88 44.53,45.34 v2(44.53,45.54) 44.54,45.55 U4.3 ; U4.9 46.49,43.45 45.97,43.97 v2(44.53,43.97)
TC_74125_SPARE_I_TP: length 25.6
  TOP w0.178: R95.2 26.75,48.67 v2(25.76,49.66)
  L3_PWR w0.178: v2(25.76,49.66) 26.01,49.91 42.93,49.91 43.41,50.39 v2(44.88,50.39)
  BOTTOM w0.178: U4.5 45.84,49.44 v2(44.88,50.39) 44.42,49.94 TP107.1
TC_74125_SPARE_O_TP: length 3.2
  BOTTOM w0.178: TP108.1 46.49,50.37 U4.6
TC_EXTAL_TP: length 3
  BOTTOM w0.178: TP102.1 33.35,43.26 33.98,43.88 U6.10
TC_SDA_USB_ID_TP: length 7.1
  TOP w0.178: v2(6.2,38.05) 6.21,38.06 J15.4
  BOTTOM w0.178: v2(6.2,38.05) 6.2,39.09 4.95,40.34 TP100.1
TC_XTAL_TP: length 3.8
  BOTTOM w0.178: TP101.1 34.01,42.11 34.01,43.08 34.32,43.38 U6.9
TGT_PWR: length 73.9
  TOP w0.178: J11.13 J11.11 v1(1.7,52.43)
  L2_GND w0.178: v1(1.7,52.43) 2.49,52.43 6.53,56.46 12.67,56.46 v2(28.3,40.84)
  L3_PWR w0.178: v2(28.3,40.84) 28.3,42.06 29.59,43.36 50.57,43.36 51.28,42.65 v2(51.28,38.43) 56.74,38.43 J12.1
UART1_CTS_TGTMCU: length 9.6
  BOTTOM w0.178: U6.22 38.57,48.02 41.27,50.72 41.27,51.97 43.56,54.25 R90.1
UART1_RST_TGTMCU: length 8.6
  BOTTOM w0.178: U6.23 39.07,47.99 41.66,50.57 41.66,51.66 43.21,53.21 R91.1
UART1_RX_TGTMCU: length 6.6
  BOTTOM w0.178: U6.25 40.22,48.02 43.38,51.18 R89.1
UART1_TX_TGTMCU: length 7.5
  BOTTOM w0.178: U6.24 39.57,47.93 42.09,50.44 42.09,51.31 42.98,52.2 R88.1
V_EXT: length 18.7
  TOP w0.508: J28.1 27.18,31.64 26.17,30.63 23.24,30.63 20.99,28.38 Q1.2 20.99,21.07 20.49,20.57 v2(19.83,20.57)
V_LED: length 111.6
  TOP w0.508: v2(50.09,36.75) 50.04,36.8 50.04,44.6 48.26,46.38 D7.A v2(48.26,47.98) ; D4.A 12.29,46.09 v2(12.29,45.06) ; v2(40.03,31.5) 42.29,31.5 43.21,30.58 v2(43.21,24.94) 42.16,24.94 40.23,23.01 R4.2 ; D5.A v2(48.26,24.94) ; D8.A 48.41,53.57 v2(49.66,54.81) ; R46.1 v2(12.57,54.64) ; v2(48.26,37.52) D6.A
  L2_GND w0.508: v2(12.57,54.64) 12.57,45.34 v2(12.29,45.06)
  L3_PWR w0.508: v2(43.21,24.94) v2(48.26,24.94) ; v2(40.03,31.5) 38.56,32.97 22.12,32.97 21.34,33.76 21.34,42.04 18.31,45.06 v2(12.29,45.06)
  BOTTOM w0.508: v2(48.26,47.98) 49.66,49.38 v2(49.66,54.81) ; v2(48.26,37.52) 49.33,37.52 v2(50.09,36.75) 50.34,36.5 50.34,32.49 48.26,30.4 v2(48.26,24.94) ; v2(43.21,24.94) TP4.1
V_MAIN: length 21.7
  TOP w0.508: SW5.1 5.64,28.57 14.05,28.57 16.64,31.17 v2(16.64,32.82) 16.87,32.82 D1.C 18.31,34.21 D3.C
  BOTTOM w0.178: v2(16.64,32.82) 16.64,31.55 TP1.1
V_MCU: length 211.6
  TOP w0.178: v1(18.21,14.78) 15.88,14.78 12.93,17.73 11.07,17.73 v1(10.26,18.54) ; C13.1 56.49,17.07 v2(56.49,17.78) 56.52,17.81 R12.1 ; v2(55.88,26.8) 55.88,26.07 L2.2 ; v2(30.98,55.58) 29.41,55.58 27,57.99 R23.1 26.26,59.05 v2(26.26,59.46) 26.26,65.28 27.81,66.83 v2(27.81,67.44) ; R565.2 v2(63.8,42.37) ; U3.25 61.39,26.06 61.82,26.49 61.82,28.17 61.43,28.56 U3.20 59.73,28.56 C8.1 C9.1 58.04,28.78 57.76,29.06 57.76,31.62 C7.1 58.47,31.78 v2(58.9,31.34) ; U13.6 64.14,47.35 v2(64.29,47.5) 64.54,47.75 v2(64.54,51.99) R552.1 R555.1 R554.1 R553.1 69.75,51.16 69.75,49.78 R563.2 ; v2(69.85,20.78) C14.1 68.3,21.36 C46.1 66.78,22.02 C47.1 66.2,22.03 U3.38 ; J11.1 3.56,59.97 v2(3.66,60.07) 4.06,60.48 R26.1 ; J8.1 6.4,63.02 R25.2 v1(6.4,59.64) ; U3.32 v2(63.2,24.79)
  TOP w0.508: v2(41.25,21.44) R6.2
  L2_GND w0.178: v1(6.4,59.64) 4.09,59.64 v2(3.66,60.07) ; v2(58.9,31.34) 56.95,31.34 56.36,30.76 56.36,27.28 v2(55.88,26.8)
  L3_PWR w0.178: v1(6.4,59.64) 6.58,59.46 v2(26.26,59.46) ; v1(10.26,18.54) 6.3,22.5 6.3,23.72 5.49,24.54 5.49,31.14 3.76,32.87 3.76,59.97 v2(3.66,60.07)
  BOTTOM w0.178: v2(30.98,55.58) 30.99,55.57 R24.1 ; v1(18.21,14.78) 34.59,14.78 v2(41.25,21.44) ; v1(6.4,59.64) 9.88,56.16 R560.1 9.88,49.48 13.74,45.62 13.74,42.48 U14.6 ; v2(64.54,51.99) 64.03,51.49 TP502.1 65.28,48.77 65.28,44.6 R20.2 63.8,43.13 v2(63.8,42.37) ; R21.1 R22.1 28.68,68.3 v2(27.81,67.44)
  BOTTOM w0.508: v2(41.96,19.18) 41.5,19.63 TP6.1 41.5,21.18 v2(41.25,21.44)
V_REG: length 18
  TOP w0.178: v2(23.85,22.94) C3.1
  TOP w0.33: R2.1 25.22,21.18 U1.1
  TOP w0.508: R2.1 C3.1 25.25,22.96 C2.1 27.46,20.8 D2.A
  BOTTOM w0.178: v2(23.85,22.94) 25.25,21.54 TP3.1
V_RF: length 55.9
  TOP w0.178: U3.42 68.2,23.57 v2(68.53,23.24) 68.53,22.1 68.86,21.77 v2(68.86,21.72) ; v2(72.69,31.24) 72.69,32.16 C12.1 C11.1 C10.1 69.72,31.9 69.72,31.19 69.09,30.56 U3.55
  TOP w0.508: R8.2 v2(40.06,17.02)
  L3_PWR w0.178: v2(72.69,31.24) 72.29,31.24 69.29,28.24 69.29,26.24 68.53,25.48 v2(68.53,23.24)
  L3_PWR w0.508: v2(40.06,17.02) 41.27,18.24 54.08,18.24 55.73,16.59 66.8,16.59 68.86,18.64 v2(68.86,21.72)
  BOTTOM w0.508: TP7.1 39.65,17.42 v2(40.06,17.02)
VOUT33: length 26
  BOTTOM w0.508: SW5.5 7.47,28.91 14.35,28.91 18.99,24.26 J3.3
VOUT33_SW: length 29.3
  TOP w0.508: D14.C 30.19,26.43 v1(29.69,25.93)
  BOTTOM w0.508: v1(29.69,25.93) 18.62,25.93 14.71,29.84 9.96,29.84 8.76,31.04 5.6,31.04 SW5.6
VREG_IN: length 31.4
  TOP w0.254: U1.5 21.25,11.11 R1.1
  TOP w0.508: v1(13.74,14.35) 13.74,12.9 C1.1 18.24,11.58 v2(18.77,11.05) R1.1
  BOTTOM w0.508: v2(18.77,11.05) TP2.1 ; SW5.2 11.07,22.8 11.07,17.02 v1(13.74,14.35)
VTRG_EN: length 16.5
  BOTTOM w0.178: Q2.3 44.98,26.75 45.87,27.64 45.87,31.78 45.11,32.54 R108.2
  BOTTOM w0.508: R108.2 R551.2 R109.1 40.22,33.54 U7.3
VTRG_FAULT_B: length 10.9
  TOP w0.178: R110.2 39.29,33.17 v2(39.29,37.81)
  BOTTOM w0.178: v2(39.29,37.81) 39.65,37.81 40.22,38.38 U7.4 40.22,38.82 U6.32
XTAL_32: length 6.8
  TOP w0.178: U3.30 62.2,23.67 60.99,22.45 59.16,22.45 C24.1 58.36,21.66 Y2.2
XTAL_32M: length 5
  TOP w0.178: R15.1 70.87,34.77 70.26,34.77 68.8,33.31 U3.56
XTAL_32M_R: length 5.4
  TOP w0.178: R15.2 C22.1 70.43,38.61 Y1.3
Z_RF_N: length 2.9
  TOP w0.178: R14.2 72.67,28.3 C25.2 74.11,28.27 Z1.3
Z_RF_P: length 2.9
  TOP w0.178: Z1.4 74.01,27.25 C25.1 R13.2
N23265787: length 1.7
  TOP w0.178: D4.C 14.33,46.79 R10.1
N23279171: length 3.8
  TOP w0.178: R16.1 v2(48.26,19.86) D5.C
  BOTTOM w0.178: TP14.1 v2(48.26,19.86)
N23279177: length 5.3
  TOP w0.178: v2(48.54,33.91) 48.26,33.63 D6.C R17.1
  BOTTOM w0.178: TP15.1 49.3,34.67 v2(48.54,33.91)
N23279197: length 6.6
  TOP w0.178: v2(50.29,53.14) 48.41,51.26 D8.C 48.41,51.03 47.14,51.03 R19.1
  BOTTOM w0.178: v2(50.29,53.14) 51.66,53.14 TP17.1
N23279203: length 5.8
  TOP w0.178: D7.C R18.1 49.4,41.02 v2(49.4,40.79)
  BOTTOM w0.178: v2(49.4,40.79) 49.4,41.61 TP16.1
N23310364: length 2.9
  TOP w0.178: U3.4 66.7,32.26 67.31,32.87 R78.2
N23310371: length 3.2
  TOP w0.178: R79.2 66.37,32.28 66.2,32.11 U3.5
N23310378: length 1.3
  TOP w0.178: U3.6 65.7,32.96 R80.2
N23310385: length 2.3
  TOP w0.178: R81.2 64.69,33.35 65.15,32.89 65.15,31.71 U3.7
N23310563: length 41.9
  L3_PWR w0.178: v2(17.07,73.38) 48.59,73.38 v2(48.61,73.41)
  BOTTOM w0.178: R66.1 48.61,70.72 v2(48.61,73.41) 48.48,73.53 J16.A37 ; v2(17.07,73.38) 16.48,73.97 J16.A69
N23310622: length 56.7
  L3_PWR w0.178: v2(60.69,72.91) 60.19,72.91 59.59,73.51 58.88,73.51 58.28,72.91 v2(16.13,72.91)
  BOTTOM w0.178: v2(16.13,72.91) 16.13,72.92 15.48,73.57 J16.A70 ; R67.1 60.27,70.82 60.27,72.49 v2(60.69,72.91) 61.48,73.7 J16.A24
N23310905: length 22.8
  L3_PWR w0.178: v2(14.48,73.86) 27.64,73.86 v2(27.66,73.84)
  BOTTOM w0.178: J16.A71 v2(14.48,73.86) ; J16.A58 27.48,74.02 v2(27.66,73.84) R68.1
N23310921: length 24.4
  L3_PWR w0.178: v2(13.49,72.42) v2(26.61,72.42)
  BOTTOM w0.178: R69.1 26.59,72.4 v2(26.61,72.42) 26.48,72.54 J16.A59 ; J16.A72 13.48,72.42 v2(13.49,72.42)
N23313140: length 21
  TOP w0.178: v2(23.93,70.31) 23.24,69.62 R77.1
  L3_PWR w0.178: v2(23.93,70.31) 23.9,70.28 12.45,70.28 v2(12.32,70.15)
  BOTTOM w0.178: v2(12.32,70.15) 9.48,72.99 J16.A76
N23313187: length 68.2
  L2_GND w0.178: v2(68.63,71.17) 68.63,73.1 66.45,75.29 9.93,75.29 v2(8.48,73.84)
  BOTTOM w0.178: v2(8.48,73.84) 8.48,75.89 8.48,75.9 J16.A77 ; R75.1 68.15,70.69 v2(68.63,71.17)
N23313323: length 6.4
  TOP w0.178: J16.B38 47.48,74 v2(47.37,73.89)
  BOTTOM w0.178: v2(47.37,73.89) R64.2
N23325134: length 14.8
  TOP w0.178: J16.B23 62.48,75.03 61.01,73.56 v2(60.48,73.56) ; v2(60.48,73.56) 60.48,73.56 58.06,71.15 R65.2 ; v2(60.48,73.56) J16.B25
N23327200: length 6.4
  TOP w0.178: R12.2 58.29,22.78 60.52,22.78 U3.29
N23340195: length 3.3
  TOP w0.178: L3.1 58.5,23.65 59.91,25.06 U3.27
N23345722: length 1.7
  TOP w0.178: U3.50 70.18,28.06 R14.1
N23346446: length 1.8
  TOP w0.178: R13.1 70.13,27.56 U3.49
N23353475: length 7.2
  TOP w0.178: C20.1 69.32,35.36 v2(69.24,35.43)
  L3_PWR w0.178: J5.1 64.24,36.04 68.63,36.04 v2(69.24,35.43)
N23360966: length 4.5
  TOP w0.178: U3.26 59.73,25.56 58.98,26.31 C36.1 58.22,25.26 L2.1
N23363687: length 9.7
  TOP w0.178: J16.B27 58.5,77.04 58.5,72.87 57.4,71.78 54.36,71.78 R58.2
N23363690: length 10
  TOP w0.178: J16.B28 57.48,73.99 56.21,72.72 53.26,72.72 R60.2
N23363940: length 12.2
  BOTTOM w0.178: J16.A27 58.48,71.54 57.99,71.04 57.99,68.96 58.65,68.3 R59.1
N23363943: length 10
  TOP w0.178: v2(57.94,73.38) 56.87,72.31 53.87,72.31 R61.1
  BOTTOM w0.178: J16.A28 57.48,73.83 v2(57.94,73.38)
N23364230: length 12.3
  BOTTOM w0.178: J16.A29 56.48,71.62 55.85,70.99 55.85,66.09 R62.1
N23364481: length 75.7
  TOP w0.178: v2(15.04,71.93) 15.04,74.37 14.48,74.92 J16.B71
  L2_GND w0.178: v2(15.04,71.93) 15.04,72.87 16.69,74.52 65.89,74.52 67.69,72.72 67.69,68.88 68.76,67.82 v2(77.9,67.82)
  BOTTOM w0.178: v2(77.9,67.82) R74.2
N23364514: length 7
  TOP w0.178: R70.2 20.04,71.12 18.48,72.68 J16.B67
N23364562: length 15.3
  TOP w0.178: v2(17.6,69.22) 17.6,76.93 J16.B68 ; R71.2 24.26,68.96 v2(24,69.22)
  L3_PWR w0.178: v2(24,69.22) v2(17.6,69.22)
N23364605: length 8.2
  TOP w0.178: R73.2 13.23,71.2 v2(15.48,71.2) J16.B70
N23364648: length 17.9
  TOP w0.178: v2(25.83,69.32) 26.26,68.88 R72.2 ; J16.B69 16.59,76.95 v2(16.59,69.67)
  L3_PWR w0.178: v2(16.59,69.67) 25.53,69.67 25.83,69.37 v2(25.83,69.32)
N23364699: length 11.1
  TOP w0.178: v2(55.48,73.48) J16.B30
  BOTTOM w0.178: R63.2 52.76,70.08 v2(52.76,69.32) 52.78,69.32 55.48,72.02 v2(55.48,73.48)
N23366702: length 16.8
  TOP w0.178: U3.46 70.15,26.06 70.61,25.6 v2(71.12,25.6)
  BOTTOM w0.178: v2(71.12,25.6) 71.25,25.48 71.25,13.34 TP26.1
N23421288: length 68.2
  L2_GND w0.178: v2(11.58,71.91) 11.58,73.53 12.95,74.9 66.09,74.9 v2(68.17,72.82)
  BOTTOM w0.178: v2(11.58,71.91) 10.48,73.01 J16.A75 ; R76.1 68.17,72.75 v2(68.17,72.82)
N23440330: length 3.6
  TOP w0.178: U3.44 69.44,25.06 69.44,25.07 v2(69.52,25.07)
  BOTTOM w0.178: TP21.1 68,25.07 v2(69.52,25.07)
N23440333: length 4.6
  TOP w0.178: v2(70.1,25.45) 69.99,25.56 U3.45
  BOTTOM w0.178: TP22.1 69.72,25.83 v2(70.1,25.45)
N23460837: length 1.3
  TOP w0.178: Z1.2 C45.1
N23503244: length 41.2
  TOP w0.333: J4.1 82.37,61.67 arc(78.95,60.26) 77.54,56.85 77.54,42.04 arc(77.79,40.8) 78.49,39.75 arc(79.09,38.85) 79.3,37.79 C17.2
N23570419: length 2.9
  TOP w0.178: L4.2 10.47,22.61 D15.A
N23642836: length 15.3
  TOP w0.305: v2(29.64,11.61) 29.14,12.11 U1.8 ; v2(29.64,11.61) 29.15,11.11 U1.6 ; v2(29.64,11.61) 28.18,11.61 U1.7
  TOP w0.33: v2(29.64,11.61) 29.64,10.31 28.63,9.3 23.19,9.3 C4.1 21.69,9.53 R1.2
N23642972: length 8.3
  TOP w0.33: U1.2 24.7,12.61 24.05,13.26
  TOP w0.508: 24.05,13.26 24.05,16.97 22.55,18.47 L1.2
N23642976: length 5.4
  TOP w0.33: L1.1 21.51,13.41 23.31,11.61 U1.4
N23643006: length 14.8
  TOP w0.178: v1(27.48,15.47) 28.17,14.78 U1.10
  TOP w0.508: R2.2 23.52,21.87 R5.1 v2(21.69,21.87)
  L3_PWR w0.508: v1(27.48,15.47) 27.48,17.09 22.71,21.87 v2(21.69,21.87)
N23643076: length 3.3
  TOP w0.508: Q1.1 19.09,25.44 R7.2 19.48,25.02 R9.1
N23643080: length 2
  TOP w0.508: Q1.3 20.98,30.23 D3.A
N23643183: length 3.6
  TOP w0.508: J3.1 28.37,17.37 D2.C
N23643259: length 3
  TOP w0.508: R4.1 38.23,23.95 J2.2
N23643265: length 2.6
  TOP w0.508: J2.4 38.48,21.41 38.51,21.44 39.01,21.44 39.04,21.41 39.14,21.41 R6.1
N23643271: length 2.4
  TOP w0.508: J2.6 39.01,18.87 R8.1
N23643416: length 13.3
  TOP w0.508: J1.6 J1.4 J1.2 17.04,24.41 R7.1 18.06,30.71 D1.A
N23645388: length 4.2
  TOP w0.178: U13.3 R563.1 R564.1
N23645400: length 11.2
  TOP w0.178: R566.1 R565.1 65.1,43.1 62.81,43.1 61.62,44.3 61.62,48.16 62.08,48.62 U13.5
N23647269: length 8.8
  BOTTOM w0.508: D16.C R562.1 16.32,45.28 U14.1 16.32,41.54 17.27,40.59 U14.5
N23647277: length 33.2
  TOP w0.178: v1(40.51,51.41) v1(31.32,51.41)
  BOTTOM w0.178: v1(40.51,51.41) 40.51,50.47 38.07,48.03 U6.21 ; J30.2 25.2,50.42 R94.1 25.83,46.35 29.13,46.35 31.32,48.54 v1(31.32,51.41)
N23648037: length 4.3
  BOTTOM w0.178: C34.2 43.97,38.58 43.18,37.8 41.55,37.8 41.17,38.18 U7.5
N23648090: length 2
  BOTTOM w0.178: Q2.1 40.08,28.93 R111.2
N23648321: length 2
  TOP w0.508: L6.2 15.09,43.47 D13.A
N23648566: length 8
  BOTTOM w0.178: J29.2 18.22,39.56 U14.4
N23649169: length 27.7
  TOP w0.178: v2(19.23,60.17) v2(19.23,70.99)
  BOTTOM w0.178: R561.1 13.56,60.17 v2(19.23,60.17) ; J16.A63 22.48,71.63 21.84,70.99 v2(19.23,70.99)
N23664400: length 19.7
  TOP w0.178: U3.47 70.39,26.56 v2(70.66,26.29)
  BOTTOM w0.178: TP25.1 67.16,11.99 70.66,15.49 v2(70.66,26.29)

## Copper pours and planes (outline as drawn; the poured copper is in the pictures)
3V3_ELEV on L3_PWR: 62.29,72.58 62.25,72.49 62.26,72.44 62.25,72.37 62.75,71.87 64.12,71.87 64.21,71.92 64.2,72.03 64.49,72.59 64.78,72.03 64.77,71.92 64.86,71.87 65.15,71.87 65.24,71.92 65.24,72.02 65.36,72.49 65.84,72.4 67.84,72.4 67.94,72.47 67.92,72.58 67.87,72.63 67.84,72.69 67.83,72.72 71.63,72.72 73.05,71.15 77.14,71.15 77.29,71.3 77.6,71.32 77.62,72.69 77.6,13.61 77.44,13.61 77.44,14.12 52.98,14.12 52.72,34.72 72.97,34.72 72.97,53.26 52.98,53.26 52.98,43.18 21.89,43.18 21.89,44.12 17.86,44.12 17.91,13.49 77.62,13.49 77.62,6.91 17.04,6.91 17.04,9.19 13.21,9.19 13.21,6.91 4.27,6.93 4.24,10.55 3.23,11.58 2.27,11.58 1.75,12.04 1.52,65.79 7.16,72.77 67.76,72.72 62.83,72.72 62.82,72.71 62.62,72.58 62.39,72.6 ; 40 cut-outs
GND on TOP (solid shape): 70.43,22.07 69.37,22.07 69.37,23.55 70.46,23.55
GND on TOP (solid shape): 81.64,20.75 80.72,20.75 80.72,24.26 81.64,24.26
GND on TOP (solid shape): 71.73,32.99 69.8,32.99 69.8,33.75 70.16,34.26 71.73,34.26
GND on TOP (solid shape): 67.21,30.58 67.21,29.13 67.23,29.11 68.15,29.11 68.15,26.62 65.48,26.62 65.33,26.47 65.33,25.15 62.26,25.15 62.23,25.17 62.23,29.06 62.61,29.06 62.61,30.61 67.18,30.61
GND on BOTTOM (solid shape): 81.58,20.73 80.67,20.73 80.67,24.28 81.58,24.28
GND on TOP: outline of 124 points within 2.54,7.35 89.74,73.41 ; 40 cut-outs
GND on BOTTOM: outline of 87 points within 2.54,7.37 89.74,73.41 ; 34 cut-outs
GND on L2_GND: 12.73,1.27 4.27,1.27 4.27,10.68 3.28,11.67 1.27,11.67 1.27,68.32 3.28,68.32 4.27,69.32 4.27,79.38 72.73,79.38 72.73,73.28 75,70.92 77.27,73.28 77.27,79.38 85.73,79.38 85.73,69.97 85.14,69.98 85.14,67.61 89.73,67.63 89.74,55.5 81.61,55.5 81.61,15.34 81.56,8.56 81.58,1.24 17.27,1.27 17.27,7.37 15,9.72 12.73,7.37 ; 5 cut-outs
P5V_USB on L3_PWR: 21.06,16.03 5.54,16.03 5.54,50.44 21.06,50.44 ; 5 cut-outs
RF_ANT on TOP (solid shape): 82.6,27.97 82.09,27.97 80.98,28.24 80.98,28.57 82.09,28.83 82.6,28.83
SDA_USB_VOUT33 on L3_PWR: 51.56,33.22 21.51,33.22 21.51,42.65 51.56,42.65
V_MCU on L3_PWR: 21.06,14.12 21.06,32.87 52.7,32.87 52.7,53.09 73.13,53.09 73.18,14.22 52.7,14.12 ; 10 cut-outs

Small or netless copper shapes (teardrops, artwork), in the pictures only: 1 on BOTTOM

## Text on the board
BOTTOM: 170-27846_C | 7 OF 10 | SECONDARY SIDE
Board Geometry/Soldermask Bottom: SECONDARY SOLDERMASK | 8 OF 10
Ref Des/Silkscreen Bottom: A | SECONDARY SILKSCREEN | 9 OF 10
User.Comments: 1 OF 1 | TEST PROBE | 1/1 | 1
TOP: 4 OF 10 | PRIMARY SIDE
Board Geometry/Soldermask Top: 3 OF 10 | PRIMARY SOLDERMASK
Ref Des/Silkscreen Top: C12 | HOST | USB | DEBUGGER | RESET | A | JTAG/SWD | SDA JTAG | 2 OF 10 | PRIMARY SILKSCREEN | TWR-KW21D256
L2_GND: 5 OF 10 | L2_GND
L3_PWR: 6 OF 10 | L3_PWR
DIMENSION: .433 | 3.543 | 2.795 | R.039 | .079 | CORNERS | CHAMFERED | AT 45 DEGREES | (8X) | (2X) | 3.175 | .435 | .409 | 2.330 | .333 | PRIMARY DATUM | GRID ORIGIN | VIEW FROM PRIMARY SIDE | DETAIL C
DISPLAY_TOP: TRACE: 13.1 +/- 1 MILS | GAP: 5 MILS +/- 0.1 MILS | A -TARGET:20 MILS+/-10% | B -TARGET:18 MILS+/-10% | C -TARGET:20 MILS+/-10% | AT THIS REQUIREMENT | 6. | 5. | 24. | 8 | AS SHOWN IN DETAIL 'A'. | 24. THIS LINE(X=2886,Y=638) IS INTENTED TO BE CONNECTED TO RF_ANTENNA NET | 22. THE PCI CARD EDGE CONNECTOR FINGERS SHALL BE PLATED WITH A MINIMUM OF | ADJUSTMENT OF SUBSTRATE B IS ALLOWED TO MEET OVERALL HEIGHT REQUIREMENT | THIS LINE(X=2898,Y=405) IS INTENTED TO BE CONNECTED BETWEEN RF_ANTENNA AND GND | 23. OVERALL PCB DIELECTRIC THICKNESS ARE TARGETED  (A & C) 20 MILS+/- 10%  AND (B) 18 MILS+/- 10% | 30 MICRO INCHES OF HARD GOLD OVER 100-200 MICRO INCHES OF NICKEL BOTH SIDES OF THE BOARD | 16. | 22. | 17. | 23.
User.5: 1 OF 10 | PRIMARY SOLDER PASTE
User.6: SECONDARY SOLDER PASTE | 10 OF 10
User.23: 05-22-13 | 08-14-13 | M.W. | B | C | FLASH MEMORY/ RESET UPDATE | PWR USB MODE, U14 UPDATE | FAB-27846
User.28: 13.1+/-1mil | 50 | 7 | 25.5
User.30: FIGURE | SIZE | 7.0 | 8.0 | 12.0 | 28.0 | 31.0 | 40.0 | 63.0 | 35.0 | 53.0 | 125.0 | 34.0x30.0 | 59.0x33.0 | DRILL CHART: TOP to BOTTOM | ALL UNITS ARE IN MILS | TOLERANCE | +0.0/-8.0 | +2.0/-2.0 | +3.0/-3.0 | +3.0/-0.0 | +4.0/-4.0 | PLATED | NON-PLATED | QTY | 76 | 869 | 2 | 6 | 10 | 65 | 3 | 4
